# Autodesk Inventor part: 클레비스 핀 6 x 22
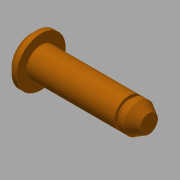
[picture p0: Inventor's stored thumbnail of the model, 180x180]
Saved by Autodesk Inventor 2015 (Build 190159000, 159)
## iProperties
IsCustomPart: 1
Created: 2017-08
Part Number: 클레비스 핀 6 x 22
Material: 강철
Description: 머리가 있는 클레비스 핀
Document SubType Name: Modeling
Standard: ISO 2341
Designer: mduedu
Standard Revision: Second edition 1986-11-01
Standards Organization: ISO
Language: ko-KR
Size Designation: B - 6 x 24
Categories: <MemberInstance><Categories><Category DisplayName="조임쇠" InternalName="e4da775c-781d-43d5-af7c-5136215cf5a6" Mnemonic="FSTN"><Category DisplayName="핀" InternalNa
Density: 7.85 g/cm^3
Appearance: 주황색
Mass: 5.79818 g
Surface Area: 6.11846 cm^2
Volume: 0.738621 cm^3
Author: mduedu
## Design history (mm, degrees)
sketch "스케치1"
  geometry: L1 (-2, 0)-(-2, 5); L2 (-2, 5)-(0, 5); L3 (0, 5)-(0, 3); L4 (0, 3)-(22, 3); L5 (22, 3)-(22, 0); L6 (-2, 0)-(22, 0); L7 (-7, 0)-(28, 0) reference; L8 (0, -1.96)-(0, 6.16) reference; C1 r 0.8 at (18.8, 0)
  constraints: 12 end point, 3 parallel, 2 collinear, 2 perpendicular, 1 centre point, 1 point on line, 1 vertical
  dimensions: "d0" = 6 diameter of L4 L6 (= NND); "d1" = 10 diameter of L2 L6 (= KOD); "d2" = 2 distance of L1.end L2.end (= KOH); "d3" = 22 distance of L3.end L4.end (= NLG); "d5" = 3.2 distance from line of L5 C1.centre (= DIST); "d6" = 1.6 diameter of C1 (= BOR)
revolve "본체" stored, may be unused: angle "d4" = 90 deg
workplane "Work Plane1"
node "작업 평면4"
sketch "스케치2"
  geometry: C1 r 3 at (0, 0) reference; C2 r 2.425 at (0, 0); 1 further point
  constraints: 1 centre point, 1 coincident
  dimensions: "d33" = 4.85 diameter of C2
extrude "돌출2" cut sketch "스케치2" distance "d34" = 0.7; taper "d35" = 0 deg
body "Solid1"
chamfer "모따기1" distance "d9" = 1 (= PHH2); stored, may be unused: angle "d10" = 45 deg (= FAWI2), second distance "d16" = 1 (= PHH2)
chamfer "모따기2" distance "d11" = 2 (= PHH1); stored, may be unused: angle "d12" = 30 deg (= FAWI1), second distance "d17" = 2 (= PHH1)
other parameters: "PHH1" = 2 [user parameter; used in 2 equation terms], "PHH2" = 1 [user parameter; used in 2 equation terms], "KOD" = 10 [user parameter; used in 1 equation term], "KOH" = 2 [user parameter; used in 1 equation term], "NND" = 6 [user parameter; used in 1 equation term], "FAWI1" = 30 deg [user parameter; used in 1 equation term], "FAWI2" = 45 deg [user parameter; used in 1 equation term], "DIST" = 3.2 [user parameter; used in 1 equation term], "BOR" = 1.6 [user parameter; used in 1 equation term], "NLG" = 22 [user parameter; used in 1 equation term], "d13" = 0, "d14" = 0, "d30" = 0, "d32" = 18
